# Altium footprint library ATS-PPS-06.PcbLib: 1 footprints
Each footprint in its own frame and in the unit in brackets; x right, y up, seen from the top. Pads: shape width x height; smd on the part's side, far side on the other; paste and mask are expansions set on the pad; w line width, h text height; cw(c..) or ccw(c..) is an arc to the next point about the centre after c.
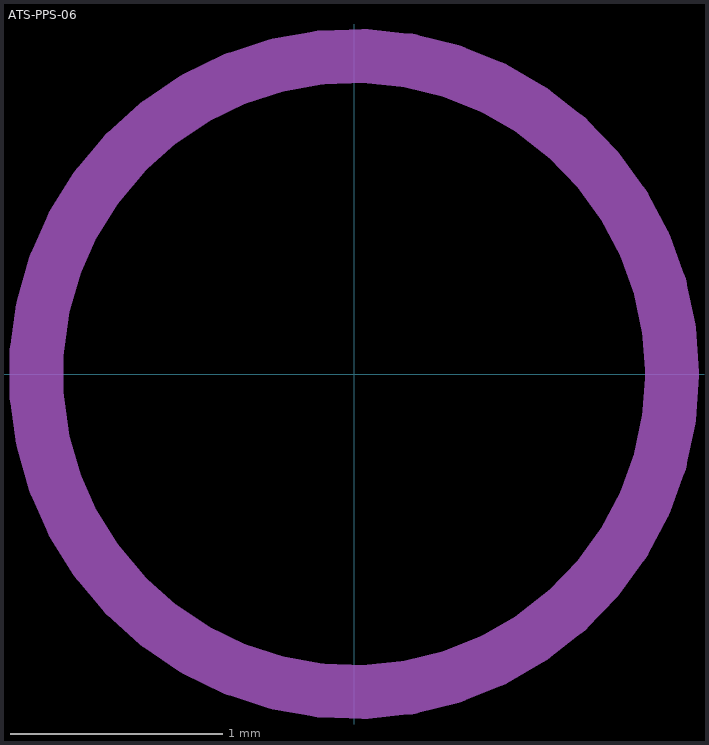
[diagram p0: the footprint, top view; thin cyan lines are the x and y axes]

## ATS-PPS-06 [mm] "ATS PUSH PIN SPRING ATS-PPS-06"
height 6.35
M5 Assembly Top:
  text ".Designator" at -0.1,0 h1.02
M13 Component Bodies Top:
  circle w0.254: c0,0 r1.5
